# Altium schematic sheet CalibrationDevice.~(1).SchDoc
size A2
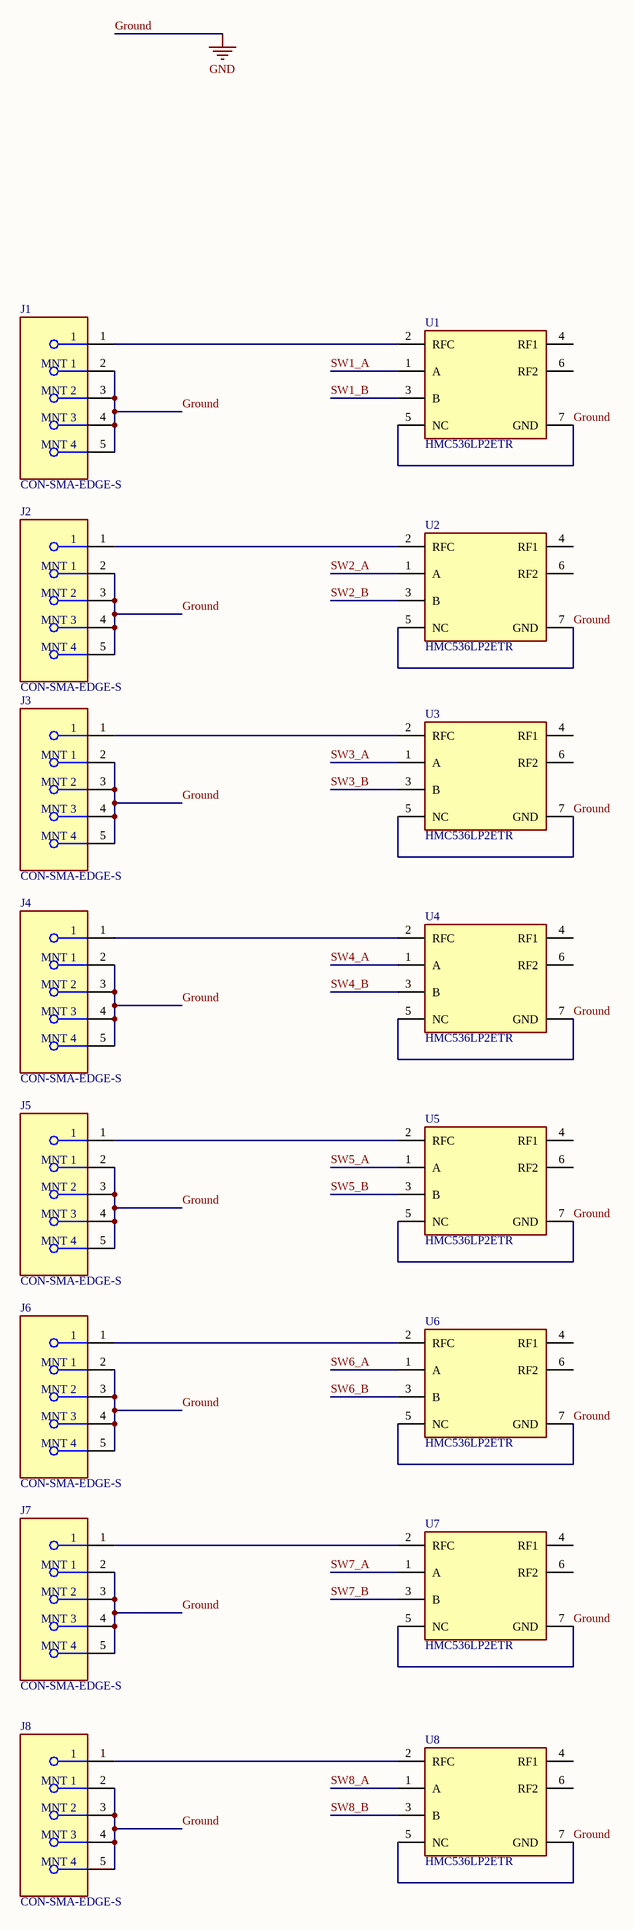
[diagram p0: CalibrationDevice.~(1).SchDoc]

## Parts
J1  CON-SMA-EDGE-S  [FP-CON-SMA-EDGE-S-MFG]
J2  CON-SMA-EDGE-S  [FP-CON-SMA-EDGE-S-MFG]
J3  CON-SMA-EDGE-S  [FP-CON-SMA-EDGE-S-MFG]
J4  CON-SMA-EDGE-S  [FP-CON-SMA-EDGE-S-MFG]
J5  CON-SMA-EDGE-S  [FP-CON-SMA-EDGE-S-MFG]
J6  CON-SMA-EDGE-S  [FP-CON-SMA-EDGE-S-MFG]
J7  CON-SMA-EDGE-S  [FP-CON-SMA-EDGE-S-MFG]
J8  CON-SMA-EDGE-S  [FP-CON-SMA-EDGE-S-MFG]
U1  HMC536LP2ETR  [FP-LP2E-MFG]
U2  HMC536LP2ETR  [FP-LP2E-MFG]
U3  HMC536LP2ETR  [FP-LP2E-MFG]
U4  HMC536LP2ETR  [FP-LP2E-MFG]
U5  HMC536LP2ETR  [FP-LP2E-MFG]
U6  HMC536LP2ETR  [FP-LP2E-MFG]
U7  HMC536LP2ETR  [FP-LP2E-MFG]
U8  HMC536LP2ETR  [FP-LP2E-MFG]

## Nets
Ground: J1.2(MNT_1) J1.3(MNT_2) J1.4(MNT_3) J1.5(MNT_4) J2.2(MNT_1) J2.3(MNT_2) J2.4(MNT_3) J2.5(MNT_4) J3.2(MNT_1) J3.3(MNT_2) J3.4(MNT_3) J3.5(MNT_4) J4.2(MNT_1) J4.3(MNT_2) J4.4(MNT_3) J4.5(MNT_4) J5.2(MNT_1) J5.3(MNT_2) J5.4(MNT_3) J5.5(MNT_4) J6.2(MNT_1) J6.3(MNT_2) J6.4(MNT_3) J6.5(MNT_4) J7.2(MNT_1) J7.3(MNT_2) J7.4(MNT_3) J7.5(MNT_4) J8.2(MNT_1) J8.3(MNT_2) J8.4(MNT_3) J8.5(MNT_4) U1.5(NC) U1.7(GND) U2.5(NC) U2.7(GND) U3.5(NC) U3.7(GND) U4.5(NC) U4.7(GND) U5.5(NC) U5.7(GND) U6.5(NC) U6.7(GND) U7.5(NC) U7.7(GND) U8.5(NC) U8.7(GND)  [also labelled GND]
SW1_A: U1.1(A)
SW1_B: U1.3(B)
SW2_A: U2.1(A)
SW2_B: U2.3(B)
SW3_A: U3.1(A)
SW3_B: U3.3(B)
SW4_A: U4.1(A)
SW4_B: U4.3(B)
SW5_A: U5.1(A)
SW5_B: U5.3(B)
SW6_A: U6.1(A)
SW6_B: U6.3(B)
SW7_A: U7.1(A)
SW7_B: U7.3(B)
SW8_A: U8.1(A)
SW8_B: U8.3(B)
NetJ1_1: J1.1 U1.2(RFC)
NetJ2_1: J2.1 U2.2(RFC)
NetJ3_1: J3.1 U3.2(RFC)
NetJ4_1: J4.1 U4.2(RFC)
NetJ5_1: J5.1 U5.2(RFC)
NetJ6_1: J6.1 U6.2(RFC)
NetJ7_1: J7.1 U7.2(RFC)
NetJ8_1: J8.1 U8.2(RFC)

Not connected (* = marked no-connect by the designer): U1 4(RF1) 6(RF2); U2 4(RF1) 6(RF2); U3 4(RF1) 6(RF2); U4 4(RF1) 6(RF2); U5 4(RF1) 6(RF2); U6 4(RF1) 6(RF2); U7 4(RF1) 6(RF2); U8 4(RF1) 6(RF2)

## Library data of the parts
J1-J8 = CMP-204357-000001-1: CONN SMA JACK STR EDGE MNT; Manufacturer: RF Solutions Ltd.; Impedance: 50Ω; Conn Orientation: Right Angle; Is Female: yes; Number Of Contacts: 1; Frequency: 18GHz; Shielding: true
U1-U8 = CMP-09141-000138-1: IC RF SWITCH SPDT 6GHZ 6DFN; P1dB: 33dBm; Impedance: 50R; Max Power Dissipation: 860mW; Insertion Loss: 0.6dB; IIP3: 52dBm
